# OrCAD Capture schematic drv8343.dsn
size B; title: DRV834x DRIVER - ANUJ NARAIN - TI
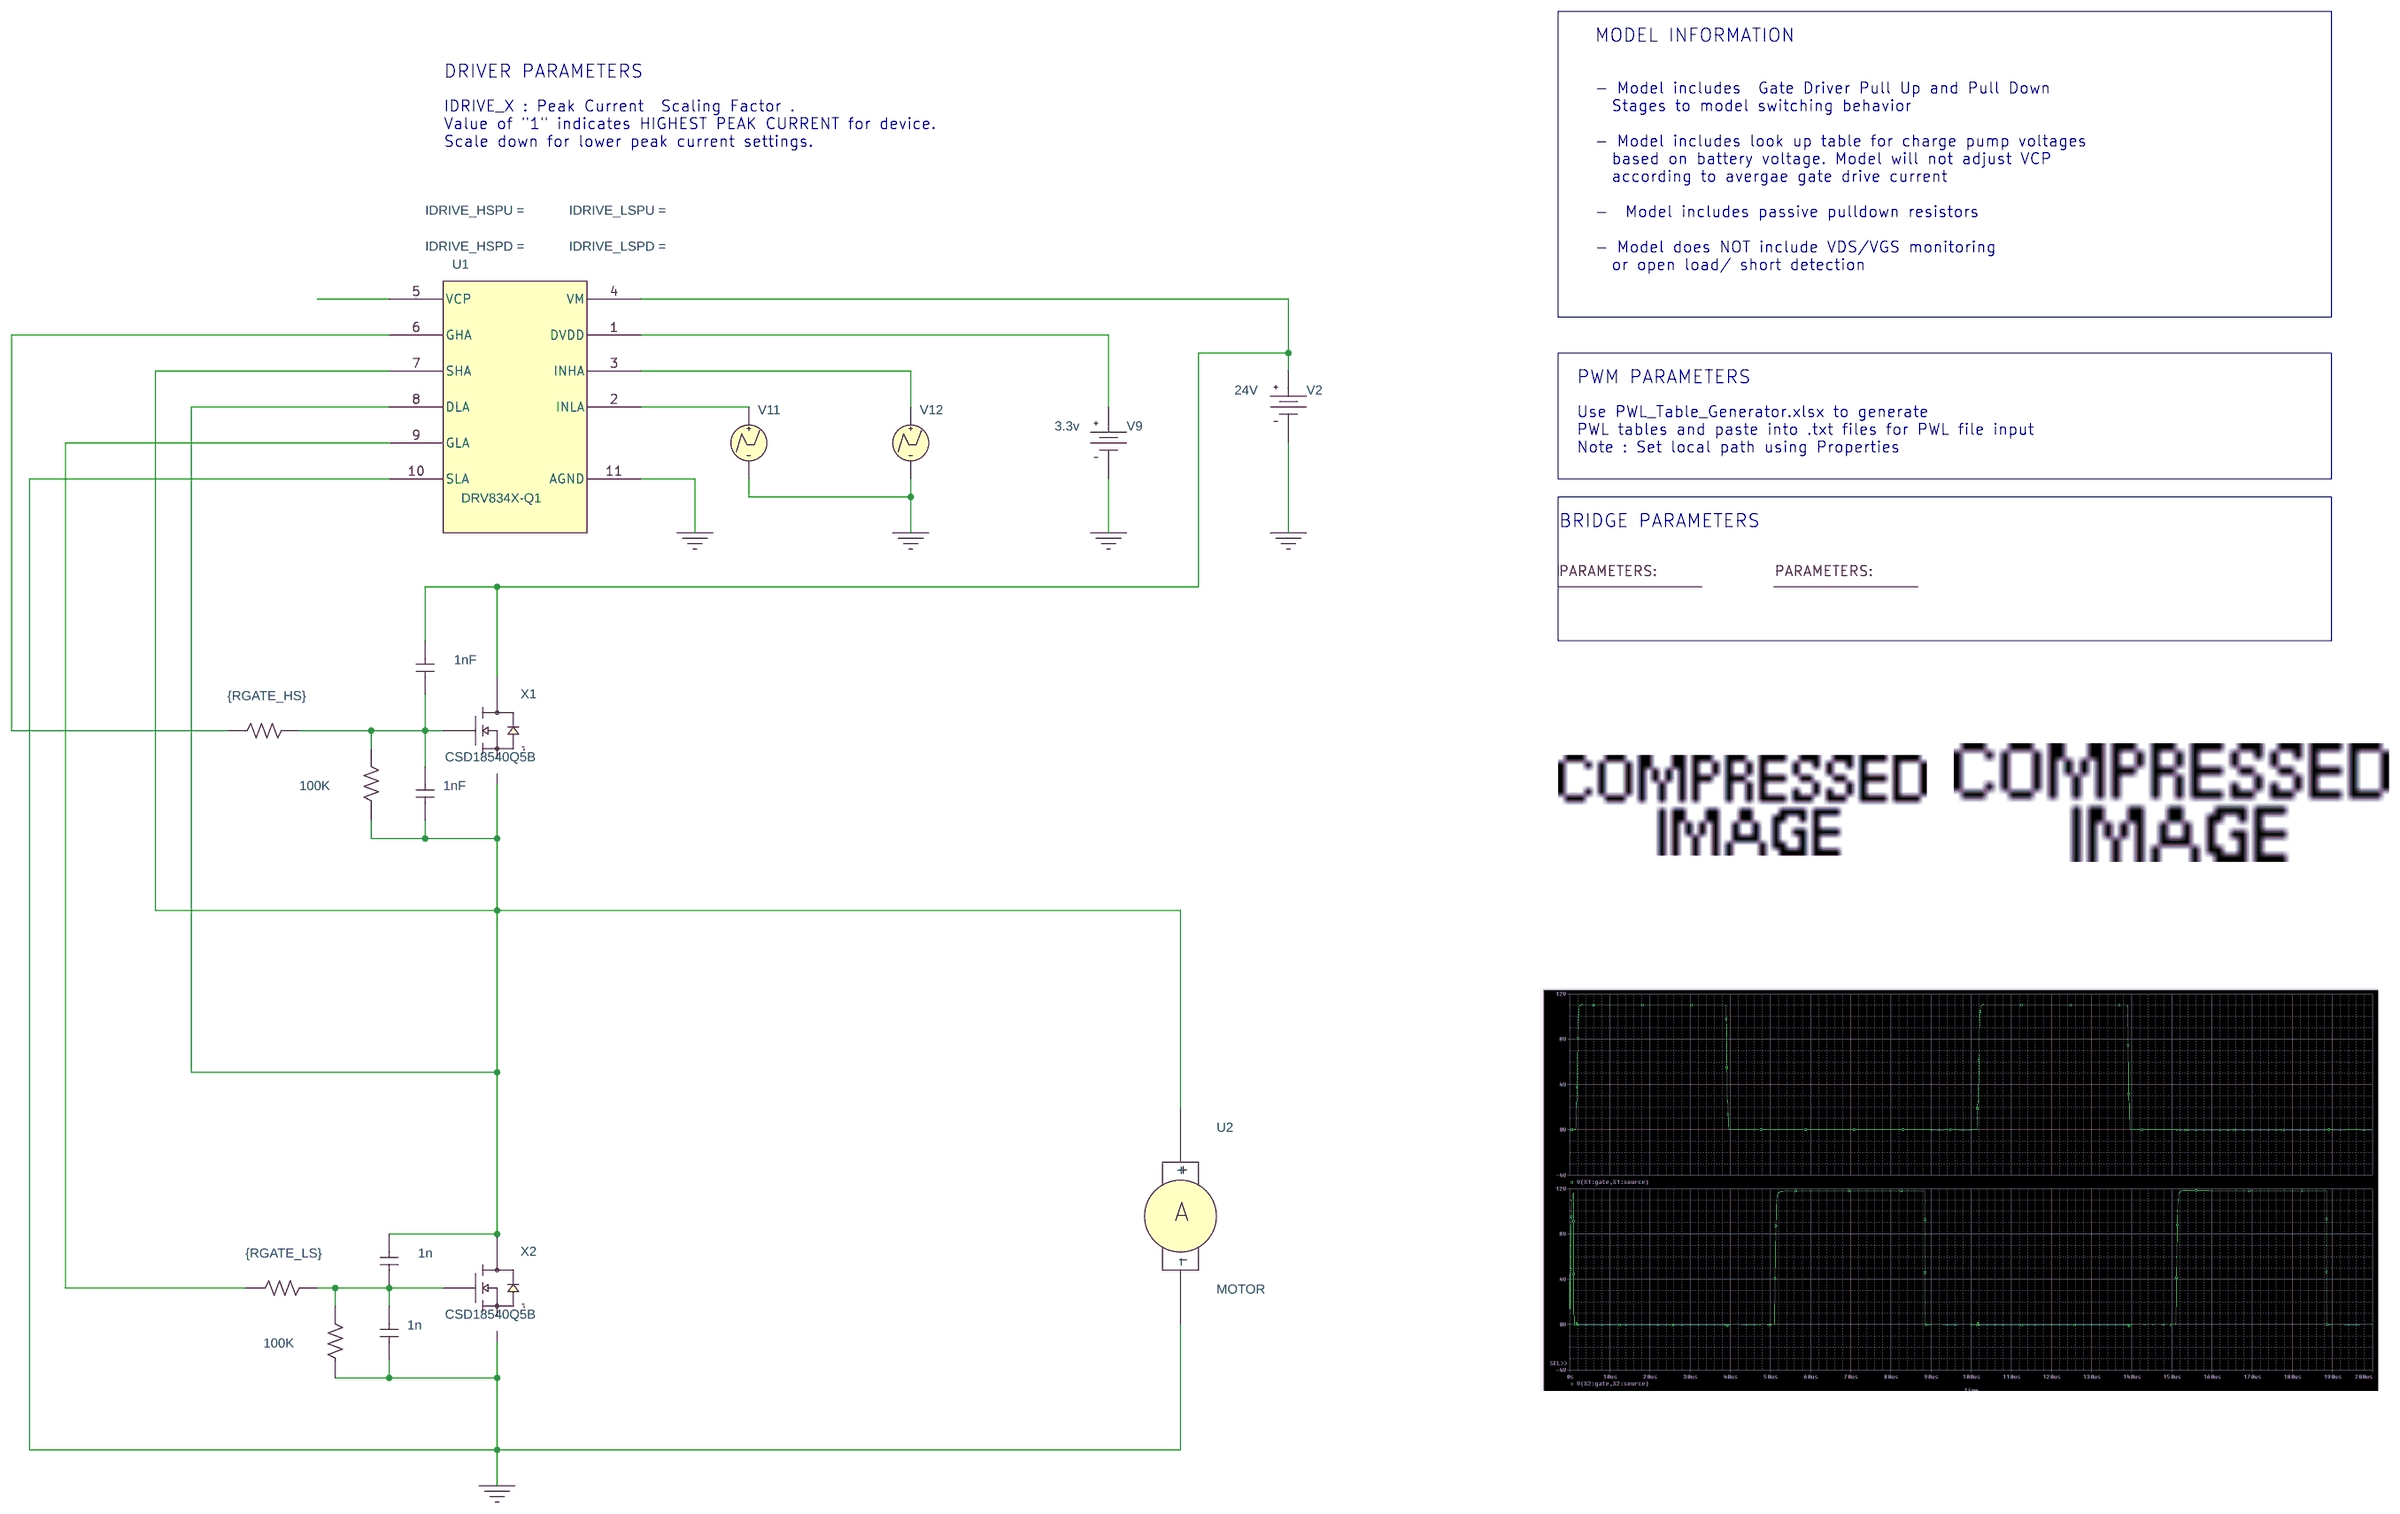
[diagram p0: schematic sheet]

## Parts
11  PARAM
12  PARAM
C_BSTA6  1nF  [RAD/CK05]
C_BSTA8  1nF  [RAD/CK05]
C_BSTA23  1n  [RAD/CK05]
C_BSTA24  1n  [RAD/CK05]
RGATE1  {RGATE_LS}  [AX/RC05]
RGATE2  {RGATE_HS}  [AX/RC05]
RVgs1  100K  [AX/RC05]
RVgs6  100K  [AX/RC05]
U1  DRV834X-Q1
U2  MOTOR
V2  VDC
V9  VDC
V11  VPWL_GENERIC
V12  VPWL_GENERIC
X1  CSD18540Q5B
X2  CSD18540Q5B

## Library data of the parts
11 = PARAM: RGATE_HS: 0.01
12 = PARAM: RGATE_LS: 0.01
C_BSTA6 C_BSTA8 C_BSTA23 C_BSTA24 = C: VOLTAGE: CMAX
RGATE1 RGATE2 RVgs1 RVgs6 = R
U1 = DRV834X_SYMBOL
U2 = MOTOR
V2 = VDC: DC: 24V
V9 = VDC: DC: 3.3v
V11 = VPWL_GENERIC: AppProp: No_reps$POINTS_TYPE_PWL$0$0; FIRST_NPAIRS: 0u 0 1u 3.3 1.01u 3.3 40u 3.3 40.01u 0; PSpiceTemplate: V^@REFDES %+ %- ?DC|DC @DC| ?AC|AC @AC| PWL ?TSF|TIME_SCALE_FACTOR=@TSF| ?VSF|VALUE_SCALE_FACTOR=@VSF| ?REPEAT_VALUE| \n+ REPEAT FOR @REPEAT_VALUE| \n+ @FIRST_NPAIRS ?SECOND_NPAIRS|\n+ @SECOND_NPAIRS ?THIRD_NPAIRS/\n+ @THIRD_NPAIRS/| ?REPEAT_VALUE| \n+ ENDREPEAT|
V12 = VPWL_GENERIC: AppProp: No_reps$POINTS_TYPE_PWL$0$0; FIRST_NPAIRS: 0u 0 45u 0 45.01u 3.3 90u 3.3 90.01u 0; PSpiceTemplate: V^@REFDES %+ %- ?DC|DC @DC| ?AC|AC @AC| PWL ?TSF|TIME_SCALE_FACTOR=@TSF| ?VSF|VALUE_SCALE_FACTOR=@VSF| ?REPEAT_VALUE| \n+ REPEAT FOR @REPEAT_VALUE| \n+ @FIRST_NPAIRS ?SECOND_NPAIRS|\n+ @SECOND_NPAIRS ?THIRD_NPAIRS/\n+ @THIRD_NPAIRS/| ?REPEAT_VALUE| \n+ ENDREPEAT|
X1 = CSD18540Q5B
X2 = CSD18540Q5B_1

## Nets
0: C_BSTA23.1 RVgs1.1 U1.10(SLA) U1.11(AGND) U2.2(-) V2.1(-) V9.1(-) V11.2(-) V12.2(-) X2.source
N15096192: C_BSTA8.1 C_BSTA24.1 RVgs6.1 U1.7(SHA) U1.8(DLA) U2.1(+) X1.source X2.drain
N15096326: RGATE1.1 U1.9(GLA)
N15100202: RGATE2.1 U1.6(GHA)
N15124582: C_BSTA6.1 U1.4(VM) V2.0(+) X1.drain
N15135072: C_BSTA6.2 C_BSTA8.2 RGATE2.2 RVgs6.2 X1.gate
N15135559: C_BSTA23.2 C_BSTA24.2 RGATE1.2 RVgs1.2 X2.gate
N15356627: U1.3(INHA) V12.1(+)
N15356644: U1.1(DVDD) V9.0(+)
N15361588: U1.2(INLA) V11.1(+)

Not connected (* = marked no-connect by the designer): U1 5(VCP)

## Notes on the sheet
- MODEL INFORMATION
- DRIVER PARAMETERS
- - Model includes  Gate Driver Pull Up and Pull Down
    Stages to model switching behavior
  - Model includes look up table for charge pump voltages
    based on battery voltage. Model will not adjust VCP
    according to avergae gate drive current
  -  Model includes passive pulldown resistors
  - Model does NOT include VDS/VGS monitoring
    or open load/ short detection
- IDRIVE_X : Peak Current  Scaling Factor .
  Value of "1" indicates HIGHEST PEAK CURRENT for device.
  Scale down for lower peak current settings.
- PWM PARAMETERS
- Use PWL_Table_Generator.xlsx to generate
  PWL tables and paste into .txt files for PWL file input
  Note : Set local path using Properties
- BRIDGE PARAMETERS
